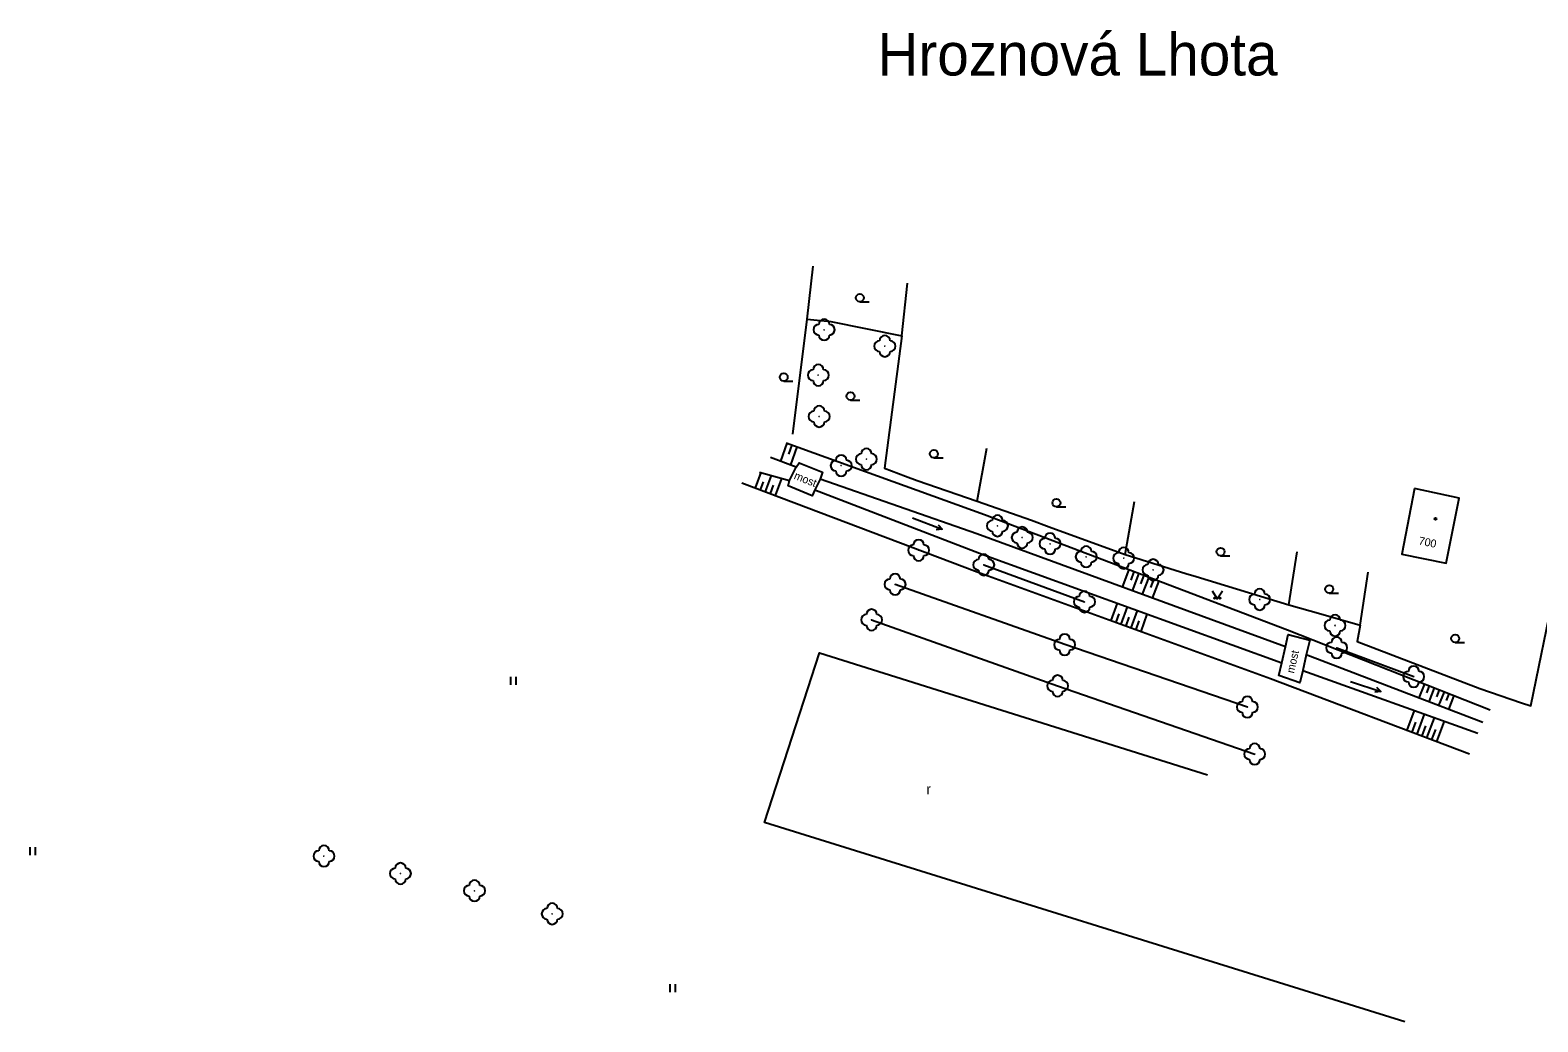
# Model space of a CAD drawing. Extents: x -544674 to -541478, y -1199076 to -1195527.
# Drawn here: x -542244.1 to -542101.8, y -1198803.8 to -1198710.2 of the extents above; entities that cross this region are included whole.
import ezdxf

# ---------------------------------------------------------------- set-up
doc = ezdxf.new("R2010")
doc.units = 0
for name, color, linetype in [('BUDOVY_NEMĚŘ', 7, 'Continuous'), ('NÁZVY_SÍDEL_JEDNOTKY', 7, 'Continuous'), ('POMOC_POPIS', 7, 'Continuous'), ('VÝŠKOPIS', 7, 'Continuous'), ('ZELEŇ', 7, 'Continuous'), ('ZN_BUDOV', 7, 'Continuous'), ('ZN_DOPLŇKOVÉ', 7, 'Continuous'), ('ZN_KULTUR', 7, 'Continuous'), ('Č_POPIS_EVID', 7, 'Continuous')]:
    doc.layers.add(name, color=color, linetype=linetype)

msp = doc.modelspace()

# ---------------------------------------------------------------- linework, layer by layer
at = {"layer": 'BUDOVY_NEMĚŘ'}
msp.add_lwpolyline([(-542113.45, -1198753.49), (-542114.65, -1198759.69), (-542110.46, -1198760.54), (-542109.23, -1198754.41), (-542113.45, -1198753.49)], dxfattribs=at)
at = {"layer": 'VÝŠKOPIS'}
for points in [[(-542172.69, -1198749.21), (-542173.3, -1198750.91)], [(-542172.78, -1198749.18), (-542154.03, -1198755.95), (-542125.45, -1198766.82), (-542106.3, -1198774.4)], [(-542172.22, -1198749.38), (-542172.53, -1198750.24)], [(-542171.75, -1198749.55), (-542172.37, -1198751.27)], [(-542171.82, -1198751.48), (-542174.23, -1198750.55)], [(-542175.66, -1198753.43), (-542175.11, -1198751.99)], [(-542175.28, -1198751.94), (-542172.44, -1198752.73)], [(-542174.72, -1198753.78), (-542174.14, -1198752.26)], [(-542176.94, -1198752.94), (-542154.72, -1198761.36), (-542127.05, -1198771.42), (-542108.24, -1198778.55)], [(-542175.19, -1198753.6), (-542174.91, -1198752.86)], [(-542174.25, -1198753.96), (-542173.95, -1198753.18)], [(-542173.78, -1198754.14), (-542173.17, -1198752.53)], [(-542170.05, -1198753.63), (-542154.11, -1198759.75), (-542125.97, -1198769.94)], [(-542125.63, -1198768.44), (-542154.76, -1198757.76), (-542169.56, -1198752.6)], [(-542140.4, -1198761.14), (-542141.03, -1198762.79)], [(-542139.93, -1198761.31), (-542140.24, -1198762.14)], [(-542139.46, -1198761.49), (-542140.09, -1198763.14)], [(-542138.99, -1198761.67), (-542139.31, -1198762.49)], [(-542138.52, -1198761.85), (-542139.15, -1198763.48)], [(-542138.06, -1198762.02), (-542138.37, -1198762.84)], [(-542137.59, -1198762.2), (-542138.21, -1198763.83)], [(-542142.08, -1198765.95), (-542141.49, -1198764.32)], [(-542141.61, -1198766.12), (-542141.32, -1198765.31)], [(-542141.14, -1198766.3), (-542140.55, -1198764.66)], [(-542140.2, -1198766.64), (-542139.61, -1198765)], [(-542140.67, -1198766.47), (-542140.38, -1198765.65)], [(-542139.73, -1198766.81), (-542139.44, -1198765.99)], [(-542139.26, -1198766.98), (-542138.67, -1198765.34)], [(-542106.99, -1198775.58), (-542123.66, -1198769.19)], [(-542124, -1198770.66), (-542107.47, -1198776.6)], [(-542112.51, -1198771.94), (-542113.04, -1198773.26)], [(-542112.05, -1198772.12), (-542112.31, -1198772.78)], [(-542111.58, -1198772.31), (-542112.1, -1198773.62)], [(-542111.12, -1198772.49), (-542111.38, -1198773.15)], [(-542110.65, -1198772.68), (-542111.17, -1198773.98)], [(-542110.19, -1198772.86), (-542110.44, -1198773.51)], [(-542109.72, -1198773.04), (-542110.23, -1198774.34)], [(-542114.14, -1198776.31), (-542113.43, -1198774.46)], [(-542113.2, -1198776.67), (-542112.49, -1198774.8)], [(-542112.27, -1198777.02), (-542111.55, -1198775.13)], [(-542113.67, -1198776.49), (-542113.32, -1198775.56)], [(-542112.73, -1198776.85), (-542112.38, -1198775.91)], [(-542111.8, -1198777.2), (-542111.44, -1198776.25)], [(-542111.33, -1198777.38), (-542110.61, -1198775.47)]]:
    msp.add_lwpolyline(points, dxfattribs=at)
at = {"layer": 'ZELEŇ'}
for points in [[(-542154.11, -1198760.69), (-542144.6, -1198764.18)], [(-542129.22, -1198774.12), (-542146.47, -1198768.23), (-542162.48, -1198762.54)], [(-542164.7, -1198765.89), (-542147.14, -1198772.12), (-542128.53, -1198778.56)], [(-542114.36, -1198803.84), (-542174.8, -1198785.03), (-542169.62, -1198769), (-542132.98, -1198780.53)], [(-542120.79, -1198768.52), (-542113.52, -1198771.25)]]:
    msp.add_lwpolyline(points, dxfattribs=at)
for centre in [(-542169.18, -1198738.5), (-542163.45, -1198740.05), (-542169.73, -1198742.79), (-542169.65, -1198746.69), (-542165.19, -1198750.72), (-542167.57, -1198751.33), (-542152.82, -1198757.01), (-542150.48, -1198758.12), (-542160.26, -1198759.32), (-542147.85, -1198758.7), (-542154.11, -1198760.69), (-542144.44, -1198759.93), (-542140.9, -1198760.06), (-542138.12, -1198761.17), (-542162.48, -1198762.54), (-542144.6, -1198764.18), (-542128.06, -1198763.96), (-542164.7, -1198765.89), (-542120.95, -1198766.42), (-542146.47, -1198768.23), (-542120.79, -1198768.52), (-542147.14, -1198772.12), (-542113.52, -1198771.25), (-542129.22, -1198774.12), (-542128.53, -1198778.56), (-542216.4, -1198788.19), (-542209.18, -1198789.84), (-542202.19, -1198791.46), (-542194.85, -1198793.64)]:
    msp.add_circle(centre, 0.0005, dxfattribs=at)
for centre, start, end in [((-542169.68, -1198738.5), 89.99999, 269.99999), ((-542169.18, -1198738), 0, 179.99999), ((-542168.68, -1198738.5), 270, 89.99999), ((-542169.18, -1198739), 179.99999, 359.99999), ((-542163.95, -1198740.05), 89.99999, 269.99999), ((-542163.45, -1198739.55), 0, 179.99999), ((-542162.95, -1198740.05), 270, 89.99999), ((-542163.45, -1198740.55), 179.99999, 359.99999), ((-542170.23, -1198742.79), 89.99999, 269.99999), ((-542169.73, -1198742.29), 0, 179.99999), ((-542169.23, -1198742.79), 270, 89.99999), ((-542169.73, -1198743.29), 179.99999, 359.99999), ((-542170.15, -1198746.69), 89.99999, 269.99999), ((-542169.65, -1198746.19), 0, 179.99999), ((-542169.15, -1198746.69), 270, 89.99999), ((-542169.65, -1198747.19), 179.99999, 359.99999), ((-542168.07, -1198751.33), 89.99999, 269.99999), ((-542167.57, -1198750.83), 0, 179.99999), ((-542167.07, -1198751.33), 270, 89.99999), ((-542165.69, -1198750.72), 89.99999, 269.99999), ((-542165.19, -1198750.22), 0, 179.99999), ((-542164.69, -1198750.72), 270, 89.99999), ((-542167.57, -1198751.83), 179.99999, 359.99999), ((-542165.19, -1198751.22), 179.99999, 359.99999), ((-542153.32, -1198757.01), 89.99999, 269.99999), ((-542152.82, -1198756.51), 0, 179.99999), ((-542152.32, -1198757.01), 270, 89.99999), ((-542152.82, -1198757.51), 179.99999, 359.99999), ((-542150.98, -1198758.12), 89.99999, 269.99999), ((-542150.48, -1198757.62), 0, 179.99999), ((-542149.98, -1198758.12), 270, 89.99999), ((-542148.35, -1198758.7), 89.99999, 269.99999), ((-542147.85, -1198758.2), 0, 179.99999), ((-542147.35, -1198758.7), 270, 89.99999), ((-542160.76, -1198759.32), 89.99999, 269.99999), ((-542160.26, -1198758.82), 0, 179.99999), ((-542159.76, -1198759.32), 270, 89.99999), ((-542150.48, -1198758.62), 179.99999, 359.99999), ((-542147.85, -1198759.2), 179.99999, 359.99999), ((-542144.94, -1198759.93), 89.99999, 269.99999), ((-542144.44, -1198759.43), 0, 179.99999), ((-542143.94, -1198759.93), 270, 89.99999), ((-542141.4, -1198760.06), 89.99999, 269.99999), ((-542140.9, -1198759.56), 0, 179.99999), ((-542140.4, -1198760.06), 270, 89.99999), ((-542160.26, -1198759.82), 179.99999, 359.99999), ((-542154.61, -1198760.69), 89.99999, 269.99999), ((-542154.11, -1198760.19), 0, 179.99999), ((-542153.61, -1198760.69), 270, 89.99999), ((-542144.44, -1198760.43), 179.99999, 359.99999), ((-542140.9, -1198760.56), 179.99999, 359.99999), ((-542138.62, -1198761.17), 89.99999, 269.99999), ((-542138.12, -1198760.67), 0, 179.99999), ((-542137.62, -1198761.17), 270, 89.99999), ((-542162.98, -1198762.54), 89.99999, 269.99999), ((-542162.48, -1198762.04), 0, 179.99999), ((-542161.98, -1198762.54), 270, 89.99999), ((-542154.11, -1198761.19), 179.99999, 359.99999), ((-542138.12, -1198761.67), 179.99999, 359.99999), ((-542162.48, -1198763.04), 179.99999, 359.99999), ((-542145.1, -1198764.18), 89.99999, 269.99999), ((-542144.6, -1198763.68), 0, 179.99999), ((-542144.1, -1198764.18), 270, 89.99999), ((-542128.56, -1198763.96), 89.99999, 269.99999), ((-542128.06, -1198763.46), 0, 179.99999), ((-542127.56, -1198763.96), 270, 89.99999), ((-542164.7, -1198765.39), 0, 179.99999), ((-542144.6, -1198764.68), 179.99999, 359.99999), ((-542128.06, -1198764.46), 179.99999, 359.99999), ((-542165.2, -1198765.89), 89.99999, 269.99999), ((-542164.7, -1198766.39), 179.99999, 359.99999), ((-542164.2, -1198765.89), 270, 89.99999), ((-542121.45, -1198766.42), 89.99999, 269.99999), ((-542120.95, -1198765.92), 0, 179.99999), ((-542120.45, -1198766.42), 270, 89.99999), ((-542146.97, -1198768.23), 89.99999, 269.99999), ((-542146.47, -1198767.73), 0, 179.99999), ((-542145.97, -1198768.23), 270, 89.99999), ((-542121.29, -1198768.52), 89.99999, 269.99999), ((-542120.95, -1198766.92), 179.99999, 359.99999), ((-542120.79, -1198768.02), 0, 179.99999), ((-542120.29, -1198768.52), 270, 89.99999), ((-542146.47, -1198768.73), 179.99999, 359.99999), ((-542120.79, -1198769.02), 179.99999, 359.99999), ((-542114.02, -1198771.25), 89.99999, 269.99999), ((-542113.52, -1198770.75), 0, 179.99999), ((-542113.02, -1198771.25), 270, 89.99999), ((-542147.64, -1198772.12), 89.99999, 269.99999), ((-542147.14, -1198771.62), 0, 179.99999), ((-542146.64, -1198772.12), 270, 89.99999), ((-542113.52, -1198771.75), 179.99999, 359.99999), ((-542147.14, -1198772.62), 179.99999, 359.99999), ((-542129.72, -1198774.12), 89.99999, 269.99999), ((-542129.22, -1198773.62), 0, 179.99999), ((-542128.72, -1198774.12), 270, 89.99999), ((-542129.22, -1198774.62), 179.99999, 359.99999), ((-542129.03, -1198778.56), 89.99999, 269.99999), ((-542128.53, -1198778.06), 0, 179.99999), ((-542128.03, -1198778.56), 270, 89.99999), ((-542128.53, -1198779.06), 179.99999, 359.99999), ((-542216.9, -1198788.19), 89.99999, 269.99999), ((-542216.4, -1198787.69), 0, 179.99999), ((-542215.9, -1198788.19), 270, 89.99999), ((-542216.4, -1198788.69), 179.99999, 359.99999), ((-542209.68, -1198789.84), 89.99999, 269.99999), ((-542209.18, -1198789.34), 0, 179.99999), ((-542208.68, -1198789.84), 270, 89.99999), ((-542209.18, -1198790.34), 179.99999, 359.99999), ((-542202.19, -1198790.96), 0, 179.99999), ((-542202.69, -1198791.46), 89.99999, 269.99999), ((-542202.19, -1198791.96), 179.99999, 359.99999), ((-542201.69, -1198791.46), 270, 89.99999), ((-542195.35, -1198793.64), 89.99999, 269.99999), ((-542194.85, -1198793.14), 0, 179.99999), ((-542194.35, -1198793.64), 270, 89.99999), ((-542194.85, -1198794.14), 179.99999, 359.99999)]:
    msp.add_arc(centre, 0.5, start, end, dxfattribs=at)
at = {"layer": 'ZN_BUDOV'}
msp.add_circle((-542111.46, -1198756.36), 0.0875, dxfattribs=at)
at = {"layer": 'ZN_DOPLŇKOVÉ'}
for points in [[(-542103.34, -1198773.73), (-542102.46, -1198774.01), (-542098, -1198752.23), (-542093.56, -1198730.86), (-542093.53, -1198730.18), (-542092.77, -1198726.52)], [(-542170.78, -1198737.49), (-542170.23, -1198732.49)], [(-542161.86, -1198739.09), (-542161.31, -1198734.09)], [(-542172.14, -1198748.36), (-542170.78, -1198737.49)], [(-542170.78, -1198737.49), (-542168.56, -1198737.73)], [(-542168.56, -1198737.73), (-542161.86, -1198739.09)], [(-542161.86, -1198739.09), (-542163.49, -1198751.58), (-542161.51, -1198752.33)], [(-542154.72, -1198754.67), (-542153.83, -1198749.67)], [(-542171.82, -1198751.48), (-542171.54, -1198751.07), (-542169.34, -1198751.96), (-542169.56, -1198752.6)], [(-542172.44, -1198752.73), (-542171.82, -1198751.48)], [(-542161.51, -1198752.33), (-542160.41, -1198752.72)], [(-542170.05, -1198753.63), (-542170.31, -1198754.18), (-542172.59, -1198753.25), (-542172.44, -1198752.73)], [(-542169.56, -1198752.6), (-542170.05, -1198753.63)], [(-542160.41, -1198752.72), (-542154.72, -1198754.67)], [(-542154.72, -1198754.67), (-542149.61, -1198756.48)], [(-542140.75, -1198759.71), (-542139.87, -1198754.71)], [(-542149.61, -1198756.48), (-542147.93, -1198757.11)], [(-542147.93, -1198757.11), (-542140.75, -1198759.71)], [(-542125.31, -1198764.47), (-542124.51, -1198759.47)], [(-542140.75, -1198759.71), (-542135.03, -1198761.52)], [(-542135.03, -1198761.52), (-542134.05, -1198761.81)], [(-542134.05, -1198761.81), (-542125.31, -1198764.47)], [(-542118.56, -1198766.39), (-542117.81, -1198761.39)], [(-542125.31, -1198764.47), (-542122.28, -1198765.31)], [(-542122.28, -1198765.31), (-542118.56, -1198766.39)], [(-542118.56, -1198766.39), (-542118.87, -1198767.94), (-542107.27, -1198772.36)], [(-542125.63, -1198768.44), (-542125.36, -1198767.27), (-542123.33, -1198767.8), (-542123.66, -1198769.19)], [(-542125.97, -1198769.94), (-542125.63, -1198768.44)], [(-542123.66, -1198769.19), (-542124, -1198770.66)], [(-542124, -1198770.66), (-542124.27, -1198771.82), (-542126.24, -1198771.15), (-542125.97, -1198769.94)], [(-542107.27, -1198772.36), (-542103.34, -1198773.73)]]:
    msp.add_lwpolyline(points, dxfattribs=at)
at = {"layer": 'ZN_KULTUR'}
for p, q in [((-542165.81, -1198735.865), (-542164.935, -1198735.865)), ((-542173, -1198743.355), (-542172.125, -1198743.355)), ((-542166.69, -1198745.145), (-542165.815, -1198745.145)), ((-542158.82, -1198750.595), (-542157.945, -1198750.595)), ((-542147.25, -1198755.225), (-542146.375, -1198755.225)), ((-542160.851, -1198756.263), (-542158.049, -1198757.337)), ((-542131.75, -1198759.835), (-542130.875, -1198759.835)), ((-542121.49, -1198763.365), (-542120.615, -1198763.365)), ((-542109.6, -1198768.025), (-542108.725, -1198768.025)), ((-542198.76, -1198772.015), (-542198.76, -1198771.265)), ((-542198.26, -1198772.015), (-542198.26, -1198771.265)), ((-542119.474, -1198771.7), (-542116.626, -1198772.64)), ((-542244.14, -1198788.115), (-542244.14, -1198787.365)), ((-542243.64, -1198788.115), (-542243.64, -1198787.365)), ((-542183.72, -1198801.045), (-542183.72, -1198800.295)), ((-542183.22, -1198801.045), (-542183.22, -1198800.295))]:
    msp.add_line(p, q, dxfattribs=at)
for points in [[(-542158.427, -1198756.924), (-542158.049, -1198757.337), (-542158.606, -1198757.391)], [(-542132.56, -1198763.14), (-542132.06, -1198763.89), (-542131.56, -1198763.14)], [(-542117.022, -1198772.246), (-542116.626, -1198772.64), (-542117.179, -1198772.721)]]:
    msp.add_lwpolyline(points, dxfattribs=at)
for centre, radius in [((-542165.81, -1198735.49), 0.375), ((-542173, -1198742.98), 0.375), ((-542166.69, -1198744.77), 0.375), ((-542158.82, -1198750.22), 0.375), ((-542147.25, -1198754.85), 0.375), ((-542131.75, -1198759.46), 0.375), ((-542132.31, -1198763.84), 0.05), ((-542131.81, -1198763.84), 0.05), ((-542121.49, -1198762.99), 0.375), ((-542109.6, -1198767.65), 0.375)]:
    msp.add_circle(centre, radius, dxfattribs=at)

# ---------------------------------------------------------------- texts
at = {"layer": 'NÁZVY_SÍDEL_JEDNOTKY'}
msp.add_text('Hroznová Lhota', height=4, dxfattribs=at).set_placement((-542164.14, -1198714.5))
at = {"layer": 'POMOC_POPIS'}
for rotation, p in [(337.81001, (-542172.09, -1198752.55)), (76.97997, (-542124.83, -1198770.98))]:
    msp.add_text('most', height=0.75, rotation=rotation, dxfattribs=at).set_placement(p)
at = {"layer": 'ZN_KULTUR'}
msp.add_text('r', height=1, dxfattribs=at).set_placement((-542159.538, -1198782.372))
at = {"layer": 'Č_POPIS_EVID'}
msp.add_text('700', height=0.75, rotation=348.24002, dxfattribs=at).set_placement((-542113.1, -1198758.76))

doc.saveas('drawing.dxf')
